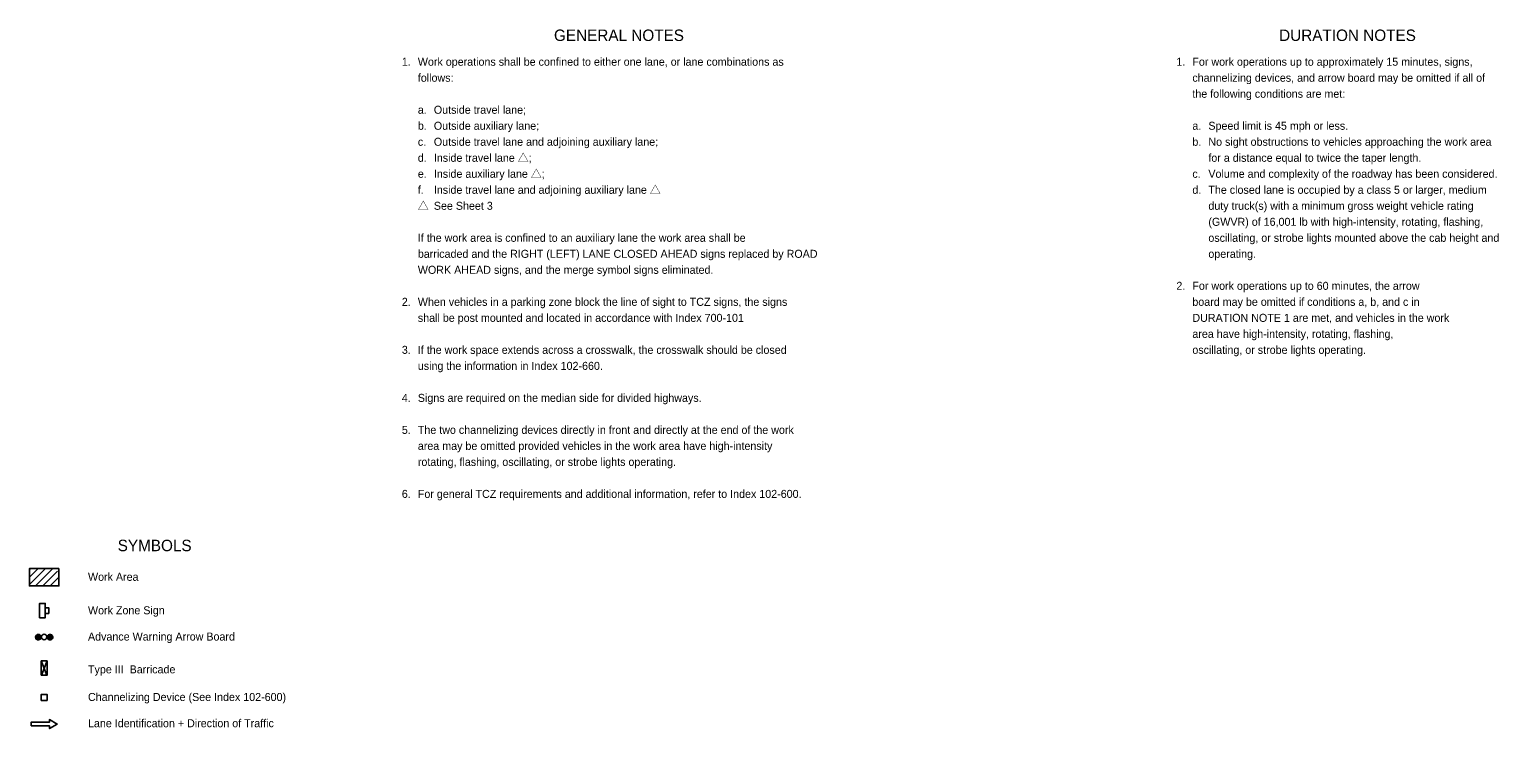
# Model space of a CAD drawing. Extents: x 10056 to 10699, y 10077 to 10382.
import ezdxf

# ---------------------------------------------------------------- set-up
doc = ezdxf.new("R2010")
doc.units = 0
for name, color, linetype in [('Default', 7, 'Continuous'), ('DSTitle', 7, 'Continuous'), ('TextMisc', 7, 'Continuous')]:
    doc.layers.add(name, color=color, linetype=linetype)

msp = doc.modelspace()

# ---------------------------------------------------------------- linework, layer by layer
at = {"layer": 'Default'}
for p, q in [((10056.35, 10139.48), (10063.38, 10146.5)), ((10056.35, 10142.68), (10060.18, 10146.5)), ((10056.35, 10145.88), (10056.97, 10146.5)), ((10059.02, 10138.94), (10066.58, 10146.5)), ((10062.21, 10138.93), (10068.71, 10145.43)), ((10065.43, 10138.94), (10069.27, 10142.79)), ((10061.54, 10106.08), (10064.03, 10099.86)), ((10064.08, 10106.13), (10061.59, 10099.9))]:
    msp.add_line(p, q, dxfattribs=at)
for points in [[(10069.27, 10146.5), (10069.27, 10138.93), (10056.35, 10138.93), (10056.35, 10146.5)], [(10063.27, 10129.39), (10063.27, 10126.88), (10064.83, 10126.88), (10064.83, 10129.39)], [(10064.11, 10088.84), (10061.51, 10088.84), (10061.51, 10091.44), (10064.11, 10091.44)]]:
    msp.add_lwpolyline(points, close=True, dxfattribs=at)
for points in [[(10060.79, 10125), (10063.28, 10125), (10063.28, 10131.23), (10060.79, 10131.23), (10060.79, 10125)], [(10061.57, 10099.87), (10064.06, 10099.87), (10064.06, 10106.1), (10061.57, 10106.1), (10061.57, 10099.87)]]:
    msp.add_lwpolyline(points, dxfattribs=at)
msp.add_circle((10062.79, 10116.56), 1.2, dxfattribs=at)
for centre, radius, start, end in [((10060.25, 10116.52), 1.2, 248.76421, 246.62419), ((10060.25, 10116.52), 1.09, 248.76421, 246.62419), ((10060.25, 10116.52), 0.972, 248.76421, 246.62419), ((10060.25, 10116.52), 0.859, 248.76421, 246.62419), ((10060.25, 10116.52), 0.745, 248.76421, 246.62419), ((10060.25, 10116.52), 0.632, 248.76421, 246.62419), ((10060.25, 10116.52), 0.519, 248.76421, 246.62419), ((10060.25, 10116.52), 0.406, 248.76421, 246.62419), ((10060.25, 10116.52), 0.293, 248.76421, 246.62419), ((10060.25, 10116.52), 0.179, 248.76421, 246.62419), ((10060.25, 10116.52), 0.066, 248.76421, 246.62419), ((10065.37, 10116.5), 1.2, 257.5828, 256.88484), ((10065.37, 10116.5), 1.09, 257.5828, 256.88484), ((10065.37, 10116.5), 0.972, 257.5828, 256.88484), ((10065.37, 10116.5), 0.859, 257.5828, 256.88484), ((10065.37, 10116.5), 0.745, 257.5828, 256.88484), ((10065.37, 10116.5), 0.632, 257.5828, 256.88484), ((10065.37, 10116.5), 0.519, 257.5828, 256.88484), ((10065.37, 10116.5), 0.406, 257.5828, 256.88484), ((10065.37, 10116.5), 0.293, 257.5828, 256.88484), ((10065.37, 10116.5), 0.179, 257.5828, 256.88484), ((10065.37, 10116.5), 0.066, 257.5828, 256.88484)]:
    msp.add_arc(centre, radius, start, end, dxfattribs=at)
at = {"layer": 'TextMisc'}
msp.add_lwpolyline([(10057.07, 10077.65), (10057.07, 10079.28), (10065.13, 10079.28), (10065.14, 10080.44), (10068.55, 10078.46), (10065.15, 10076.51), (10065.15, 10077.65)], close=True, dxfattribs=at)

# ---------------------------------------------------------------- texts
at = {"layer": 'DSTitle'}
for s, height, p in [('GENERAL NOTES', 5, (10285.77, 10377.23)), ('DURATION NOTES', 5, (10602.89, 10377.23)), ('1.', 3.5, (10219.23, 10366.4)), ('Work operations shall be confined to either one lane, or lane combinations as ', 3.5, (10226.23, 10366.4)), ('1.', 3.5, (10557.94, 10366.4)), ('For work operations up to approximately 15 minutes, signs, ', 3.5, (10564.94, 10366.4)), ('follows:', 3.5, (10226.23, 10359.4)), ('channelizing devices, and arrow board may be omitted if all of ', 3.5, (10564.94, 10359.4)), ('the following conditions are met:', 3.5, (10564.94, 10352.4)), ('a.', 3.5, (10226.23, 10345.4)), ('Outside travel lane;', 3.5, (10233.23, 10345.4)), ('b.', 3.5, (10226.23, 10338.4)), ('Outside auxiliary lane; ', 3.5, (10233.23, 10338.4)), ('a.', 3.5, (10564.94, 10338.4)), ('Speed limit is 45 mph or less.', 3.5, (10571.94, 10338.4)), ('c.', 3.5, (10226.23, 10331.4)), ('Outside travel lane and adjoining auxiliary lane;', 3.5, (10233.23, 10331.4)), ('b.', 3.5, (10564.94, 10331.4)), ('No sight obstructions to vehicles approaching the work area ', 3.5, (10571.94, 10331.4)), ('d.', 3.5, (10226.23, 10324.4)), ('Inside travel lane △;', 3.5, (10233.23, 10324.4)), ('for a distance equal to twice the taper length.', 3.5, (10571.94, 10324.4)), ('e.', 3.5, (10226.23, 10317.4)), ('Inside auxiliary lane △;', 3.5, (10233.23, 10317.4)), ('c.', 3.5, (10564.94, 10317.4)), ('Volume and complexity of the roadway has been considered.', 3.5, (10571.94, 10317.4)), ('f.', 3.5, (10226.23, 10310.4)), ('Inside travel lane and adjoining auxiliary lane △', 3.5, (10233.23, 10310.4)), ('d.', 3.5, (10564.94, 10310.4)), ('The closed lane is occupied by a class 5 or larger, medium ', 3.5, (10571.94, 10310.4)), ('△', 3.5, (10226.23, 10303.4)), ('See Sheet 3', 3.5, (10233.23, 10303.4)), ('duty truck(s) with a minimum gross weight vehicle rating ', 3.5, (10571.94, 10303.4)), ('(GWVR) of 16,001 lb with high-intensity, rotating, flashing, ', 3.5, (10571.94, 10296.4)), ('If the work area is confined to an auxiliary lane the work area shall be ', 3.5, (10226.23, 10289.4)), ('oscillating, or strobe lights mounted above the cab height and ', 3.5, (10571.94, 10289.4)), ('barricaded and the RIGHT (LEFT) LANE CLOSED AHEAD signs replaced by ROAD ', 3.5, (10226.23, 10282.4)), ('operating.', 3.5, (10571.94, 10282.4)), ('WORK AHEAD signs, and the merge symbol signs eliminated.', 3.5, (10226.23, 10275.4)), ('2.', 3.5, (10557.94, 10268.4)), ('For work operations up to 60 minutes, the arrow', 3.5, (10564.94, 10268.4)), ('2.', 3.5, (10219.23, 10261.4)), ('When vehicles in a parking zone block the line of sight to TCZ signs, the signs ', 3.5, (10226.23, 10261.4)), ('board may be omitted if conditions a, b, and c in', 3.5, (10564.94, 10261.4)), ('shall be post mounted and located in accordance with Index 700-101', 3.5, (10226.23, 10254.4)), ('DURATION NOTE 1 are met, and vehicles in the work', 3.5, (10564.94, 10254.4)), ('area have high-intensity, rotating, flashing,', 3.5, (10564.94, 10247.4)), ('3.', 3.5, (10219.23, 10240.4)), ('If the work space extends across a crosswalk, the crosswalk should be closed ', 3.5, (10226.23, 10240.4)), ('oscillating, or strobe lights operating.', 3.5, (10564.94, 10240.4)), ('using the information in Index 102-660.', 3.5, (10226.23, 10233.4)), ('4.', 3.5, (10219.23, 10219.4)), ('Signs are required on the median side for divided highways. ', 3.5, (10226.23, 10219.4)), ('5.', 3.5, (10219.23, 10205.4)), ('The two channelizing devices directly in front and directly at the end of the work ', 3.5, (10226.23, 10205.4)), ('area may be omitted provided vehicles in the work area have high-intensity ', 3.5, (10226.23, 10198.4)), ('rotating, flashing, oscillating, or strobe lights operating.', 3.5, (10226.23, 10191.4)), ('6.', 3.5, (10219.23, 10177.4)), ('For general TCZ requirements and additional information, refer to Index 102-600.', 3.5, (10226.23, 10177.4)), ('SYMBOLS', 5, (10094.97, 10154.1)), ('Work Area', 3.5, (10081.98, 10141.14)), ('Work Zone Sign', 3.5, (10081.98, 10126.51)), ('Advance Warning Arrow Board', 3.5, (10081.98, 10115.01)), ('Type III  Barricade', 3.5, (10081.98, 10100.68)), ('Channelizing Device (See Index 102-600)', 3.5, (10081.98, 10088.59)), ('Lane Identification + Direction of Traffic', 3.5, (10081.98, 10077.11))]:
    msp.add_text(s, height=height, dxfattribs=at).set_placement(p)

doc.saveas('drawing.dxf')
